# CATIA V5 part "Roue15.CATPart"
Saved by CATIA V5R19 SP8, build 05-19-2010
Part number: Roue15
Bounding box of the stored display mesh (mm): x -150 to -130, y -40.208 to 19.792, z -4.266 to 55.734
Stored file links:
  G:\EU_thinkMotion\CFAO_2010\MMS_groupe2\MMS_groupe2\A reprendre\jcauchy\Roue15.CATPart
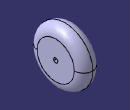
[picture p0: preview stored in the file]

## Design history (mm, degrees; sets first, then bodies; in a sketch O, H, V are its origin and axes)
Parameters
  Rayonroue_roue15 = 30 mm
  Rayoncongeroue_roue15 = 10 mm
  Largeurroue_roue15 = 10 mm
  Rayonfixation_roue15 = 2.5 mm
Set1
  Plane1: stored without definition
  Sketch1 on Plane1, origin (-140, 0, 0), H (0, -1, 0), V (0, 0, 1)
    circle A1 centre (10.2078, 25.7342) radius 30
    point P1 (10.2078, 25.7342)
    reference projected point E1 (10.2078, 25.7342) from Point1
    radius A1 = 30 {= Rayonroue_roue15}
    distance E1 P1 = 0
  Point1: stored without definition
Body1 (main body)
  Pad1: profile Sketch1, direction (-1, 0, 0), length 10 {= Largeurroue_roue15}, mirrored extent
  Fillet1: radius 10 {= Rayoncongeroue_roue15}, on edge [face of Pad1 from Sketch1.A1 | end face of Pad1]
  Fillet2: radius 10 {= Rayoncongeroue_roue15}, on edge [start face of Pad1 | face of Pad1 from Sketch1.A1]
  Sketch2 on end face of Pad1, origin (-150, -10.2078, 25.7342), H (0, 1, 0), V (0, 0, -1)
    point P1 (0, 0)
  Hole1: placed by Sketch2, at (-150, -10.2078, 25.7342) direction (1, 0, 0), diameter 5 {= Rayonfixation_roue15 *2}, through (limit type 3)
